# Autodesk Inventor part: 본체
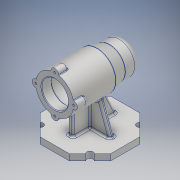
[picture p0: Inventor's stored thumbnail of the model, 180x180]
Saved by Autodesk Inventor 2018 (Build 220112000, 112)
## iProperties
Created: 2019-12
Part Number: 본체
Material: 알루미늄 6061
Document SubType Name: Modeling
Designer: Administrator
Density: 2.70108 g/cm^3
Appearance: 알루미늄 - 평지
Mass: 734 g
Surface Area: 721.545 cm^2
Volume: 271.743 cm^3
Author: Administrator
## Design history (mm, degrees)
sketch "스케치1"
  geometry: L1 (56, -23.196)-(23.196, -56); L2 (23.196, -56)-(-23.196, -56); L3 (-23.196, -56)-(-56, -23.196); L4 (-56, -23.196)-(-56, 23.196); L5 (-56, 23.196)-(-23.196, 56); L6 (-23.196, 56)-(23.196, 56); L7 (23.196, 56)-(56, 23.196); L8 (56, 23.196)-(56, -23.196); L9 (39.598, 39.598)-(0, 0); L10 (0, 0)-(56, 0); A1 r 56 centre (0, 0) between (39.598, 39.598) and (56, 0); 6 further points
  constraints: 20 end point, 2 coincident, 2 point on circle, 1 centre point, 1 horizontal, 1 midpoint, 1 vertical alignment, 22 other
  dimensions: "d0" = 56 distance from line of L8 point (0, 0); "d1" = 45 deg angle of L10 L9; "d4" = 360 deg dimension on point (0, 0) L9.start (derived); "d6" = 112 diameter of A1
extrude "돌출1" new body sketch "스케치1" distance "d7" = 10; taper "d8" = 0 deg
hole "구멍1" sketch "스케치1" diameter "d9" = 10; stored, may be unused: countersink angle "d13" = 90 deg, drill point angle "d15" = 118 deg; dims "d10" = 6, "d11" = 4, "d12" = 2, "d14" = 8
sketch "스케치2"
  geometry: L1 (43.134, 10)-(56, 10) reference; L2 (36, 10)-(6.882, 90); L3 (6.882, 90)-(0, 90); L4 (0, 90)-(0, 10); L5 (-23.196, 10)-(23.196, 10) reference; L6 (36, 10)-(0, 10); L7 (56, 0)-(56, 10) reference; 1 further point
  constraints: 8 end point, 1 collinear, 1 midpoint, 1 parallel, 1 point on line
  dimensions: "d16" = 20 distance from line of L7 L2.start; "d17" = 110 deg angle of L2 L1; "d18" = 80 distance between parallel lines of L5 L3
extrude "돌출2" join sketch "스케치2" stored distance "d19" = 8; taper "d20" = 0 deg
sketch "스케치3"
  geometry: L1 (38, 10)-(5.358, 80); L2 (5.358, 80)-(-31, 80); L3 (34.598, 10)-(43.134, 10) reference; L4 (-31, 80)-(-31, 10); L5 (-43.134, 10)-(-56, 10) reference; L6 (-31, 10)-(38, 10); L7 (43.134, 0)-(43.134, 10) reference; L8 (-56, 0)-(-56, 10) reference; L9 (56, 0)-(56, 10) reference; L10 (56, 10)-(43.134, 10) reference; L11 (-23.196, 0)-(23.196, 0) reference; 2 further points
  constraints: 8 end point, 2 perpendicular, 1 parallel, 1 point on line
  dimensions: "d21" = 25 distance between parallel lines of L8 L4; "d22" = 18 distance from line of L9 L1.start; "d23" = 115 deg angle of L10 L1; "d24" = 80 distance between parallel lines of L11 L2
extrude "돌출3" join sketch "스케치3" stored distance "d25" = 8; taper "d26" = 0 deg
sketch "스케치4"
  geometry: L1 (-56, 80)-(11, 80); L2 (11, 80)-(11, 110); L3 (11, 110)-(-56, 110); L4 (-56, 110)-(-56, 80); L5 (31, 80)-(56, 80); L6 (56, 80)-(56, 105); L7 (56, 105)-(31, 105); L8 (31, 105)-(31, 80); L9 (11, 110)-(31, 105); L10 (11, 80)-(31, 80); L11 (23.196, 0)-(-23.196, 0) reference; 2 further points
  constraints: 20 end point, 4 parallel, 2 horizontal, 2 perpendicular, 1 collinear, 1 point on line, 1 vertical alignment
  dimensions: "d27" = 60 diameter of L3 L1; "d28" = 50 diameter of L7 L5; "d29" = 25 distance between parallel lines of L6 L8; "d30" = 45 distance between parallel lines of L2 L6; "d31" = 112 distance between parallel lines of L6 L4; "d32" = 80 distance between parallel lines of L11 L1
revolve "회전1" sketch "스케치4" stored, may be unused: angle "d33" = 90 deg
sketch "스케치5"
  geometry: L1 (-56, 50)-(-56, 110) reference; L2 (-56, 80)-(-41, 80); L3 (-41, 80)-(-41, 101); L4 (-41, 101)-(-56, 101); L5 (-56, 101)-(-56, 80); L6 (-41, 80)-(13, 80); L7 (13, 80)-(13, 101); L8 (10, 104)-(-38, 104); L9 (-41, 101)-(-41, 80); L10 (13, 80)-(25, 80); L11 (25, 80)-(25, 100.7); L12 (13, 101)-(13, 80); L13 (25, 80)-(43, 80); L14 (43, 80)-(43, 97.2); L15 (42.7, 97.5)-(25, 97.5); L16 (25, 97.5)-(25, 80); L17 (43, 80)-(47, 80); L18 (47, 80)-(47, 95.7); L19 (46.7, 96)-(43, 96); L20 (43, 96)-(43, 80); L21 (47, 80)-(50, 80); L22 (50, 80)-(50, 90.5); L23 (50, 90.5)-(47, 90.5); L24 (47, 90.5)-(47, 80); L25 (24.7, 101)-(13, 101); L26 (11, 50.268)-(11, 110) reference; A1 r 3 centre (-38, 101) between (-38, 104) and (-41, 101); A2 r 3 centre (10, 101) between (13, 101) and (10, 104); A3 r 0.3 centre (24.7, 100.7) between (25, 100.7) and (24.7, 101); A4 r 0.3 centre (42.7, 97.2) between (43, 97.2) and (42.7, 97.5); A5 r 0.3 centre (46.7, 95.7) between (47, 95.7) and (46.7, 96); 6 further points
  constraints: 48 end point, 11 parallel, 11 point on line, 10 point on circle, 10 tangent, 7 perpendicular, 6 horizontal, 5 centre point, 3 equal radius, 1 midpoint
  dimensions: "d34" = 42 diameter of L4 L2; "d35" = 48 diameter of L8 L6; "d36" = 35 diameter of L15 L13; "d37" = 32 diameter of L19 L17; "d38" = 21 diameter of L23 L21; "d39" = 15 distance of L3.end L4.end; "d40" = 54 distance of point (13, 104) point (-41, 104); "d41" = 12 distance of point (25, 101) L12.start; "d42" = 18 distance of point (43, 97.5) L15.end; "d43" = 3 distance of L22.end L23.end; "d44" = 4 distance of point (47, 96) L19.end; "d70" = 3 radius of A1; "d71" = 0.3 radius of A3
revolve "회전2" sketch "스케치5" stored, may be unused: angle "d45" = 90 deg
sketch "스케치6"
  geometry: C1 r 6 at (0, 30); A1 r 30 centre (0, 0) between (4, -29.732) and (-4, -29.732) reference; 1 further point
  constraints: 1 centre point, 1 point on circle
  dimensions: "d46" = 12 diameter of C1
extrude "돌출4" join sketch "스케치6" distance "d47" = 16; taper "d48" = 0 deg
sketch "스케치7" dims "d49" = 60
  geometry: A1 r 30 centre (0, -30) between (4, -59.732) and (-4, -59.732) reference; 3 further points
  constraints: 1 coincident, 1 vertical alignment, 2 other
hole "구멍2" sketch "스케치7" at (0, 0) diameter "d50" = 3.242; stored, may be unused: countersink angle "d54" = 90 deg, drill point angle "d56" = 118 deg; dims "d51" = 8, "d52" = 4, "d53" = 2, "d55" = 11
fillet "모깎기1" dims "d60" = 3
fillet "모깎기2" dims "d61" = 3
fillet "모깎기3" dims "d62" = 3
fillet "모깎기4" dims "d63" = 3
fillet "모깎기5" dims "d64" = 3
fillet "모깎기6" dims "d65" = 1
fillet "모깎기7" dims "d69" = 3
chamfer "모따기1" distance "d72" = 1; stored, may be unused: second distance "d73" = 2, angle "d74" = 45 deg
node "작업 평면1"
sketch "스케치8"
  geometry: L1 (56, 55)-(56, 105) reference; L2 (-56, 86.771)-(-56, 109.226) reference; 3 further points
  constraints: 1 midpoint, 1 other
  dimensions: "d79" = 41 distance from line of L2 point (-15, 80)
feature "엠보싱1" sketch "스케치8" dims "d0" = 56, "d1" = 45 deg, "d4" = 360 deg (derived), "d6" = 112, "d77" = 0.5, "d78" = 0
fillet "모깎기8" dims "d80" = 10
node "솔리드1"
mirror "미러1"
pattern_circular "원형 패턴1" dims angle "d58" = 360 deg
pattern_circular "원형 패턴2" dims angle "d67" = 360 deg
